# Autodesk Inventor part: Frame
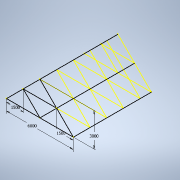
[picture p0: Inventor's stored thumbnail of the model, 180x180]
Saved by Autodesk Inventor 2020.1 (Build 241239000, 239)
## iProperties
Created: 2019-10
Part Number: Frame
Material: Generic
Document SubType Name: Modeling
Designer: Synergysoft Dell02
Density: 1 g/cm^3
Appearance: Default
Author: Synergysoft Dell02
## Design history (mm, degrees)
sketch "Sketch1"
  geometry: L1 (-3000, 0)-(3000, 0); L2 (3000, 0)-(0, 3000); L3 (0, 3000)-(-3000, 0); L4 (-1500, 1500)-(0, 0); L5 (1500, 1500)-(0, 0); L6 (-1500, 1500)-(1500, 1500); 1 further point
  constraints: 12 end point, 3 midpoint, 1 coincident, 1 horizontal, 1 vertical alignment
  dimensions: "d0" = 6000 distance of L1.start L1.end; "d1" = 3000 distance of point (0, 0) L2.end; "d7" = 1500 horizontal distance of L4.start L1.start; "d8" = 1500 horizontal distance of L1.end L5.start
workplane "Work Plane5"
  workplane "Work Plane4"
sketch "Sketch2"
  geometry: L1 (-3000, 0)-(3000, 0) reference; L2 (0, 3000)-(-3000, 0) reference; L3 (3000, 0)-(0, 3000) reference; 1 further point
sketch "Sketch3"
  geometry: L1 (0, 3000)-(-3000, 0) reference; L2 (3000, 0)-(0, 3000) reference; L3 (-3000, 0)-(3000, 0) reference; 1 further point
sketch "Sketch4"
  geometry: L1 (0, 3000)-(-3000, 0) reference; L2 (3000, 0)-(0, 3000) reference; L3 (-3000, 0)-(3000, 0) reference; 1 further point
sketch "Sketch5"
  geometry: L1 (0, 3000)-(-3000, 0) reference; L2 (3000, 0)-(0, 3000) reference; L3 (-3000, 0)-(3000, 0) reference; 1 further point
sketch "Sketch6"
  geometry: L1 (0, 3000)-(-3000, 0) reference; L2 (3000, 0)-(0, 3000) reference; L3 (-3000, 0)-(3000, 0) reference; L4 (-1500, 1500)-(0, 0) reference; L5 (-1500, 1500)-(1500, 1500) reference; L6 (1500, 1500)-(0, 0) reference; 1 further point
sketch "3D Sketch1"
sketch "3D Sketch2"
workplane "Work Plane1"
workplane "Work Plane2"
workplane "Work Plane3"
